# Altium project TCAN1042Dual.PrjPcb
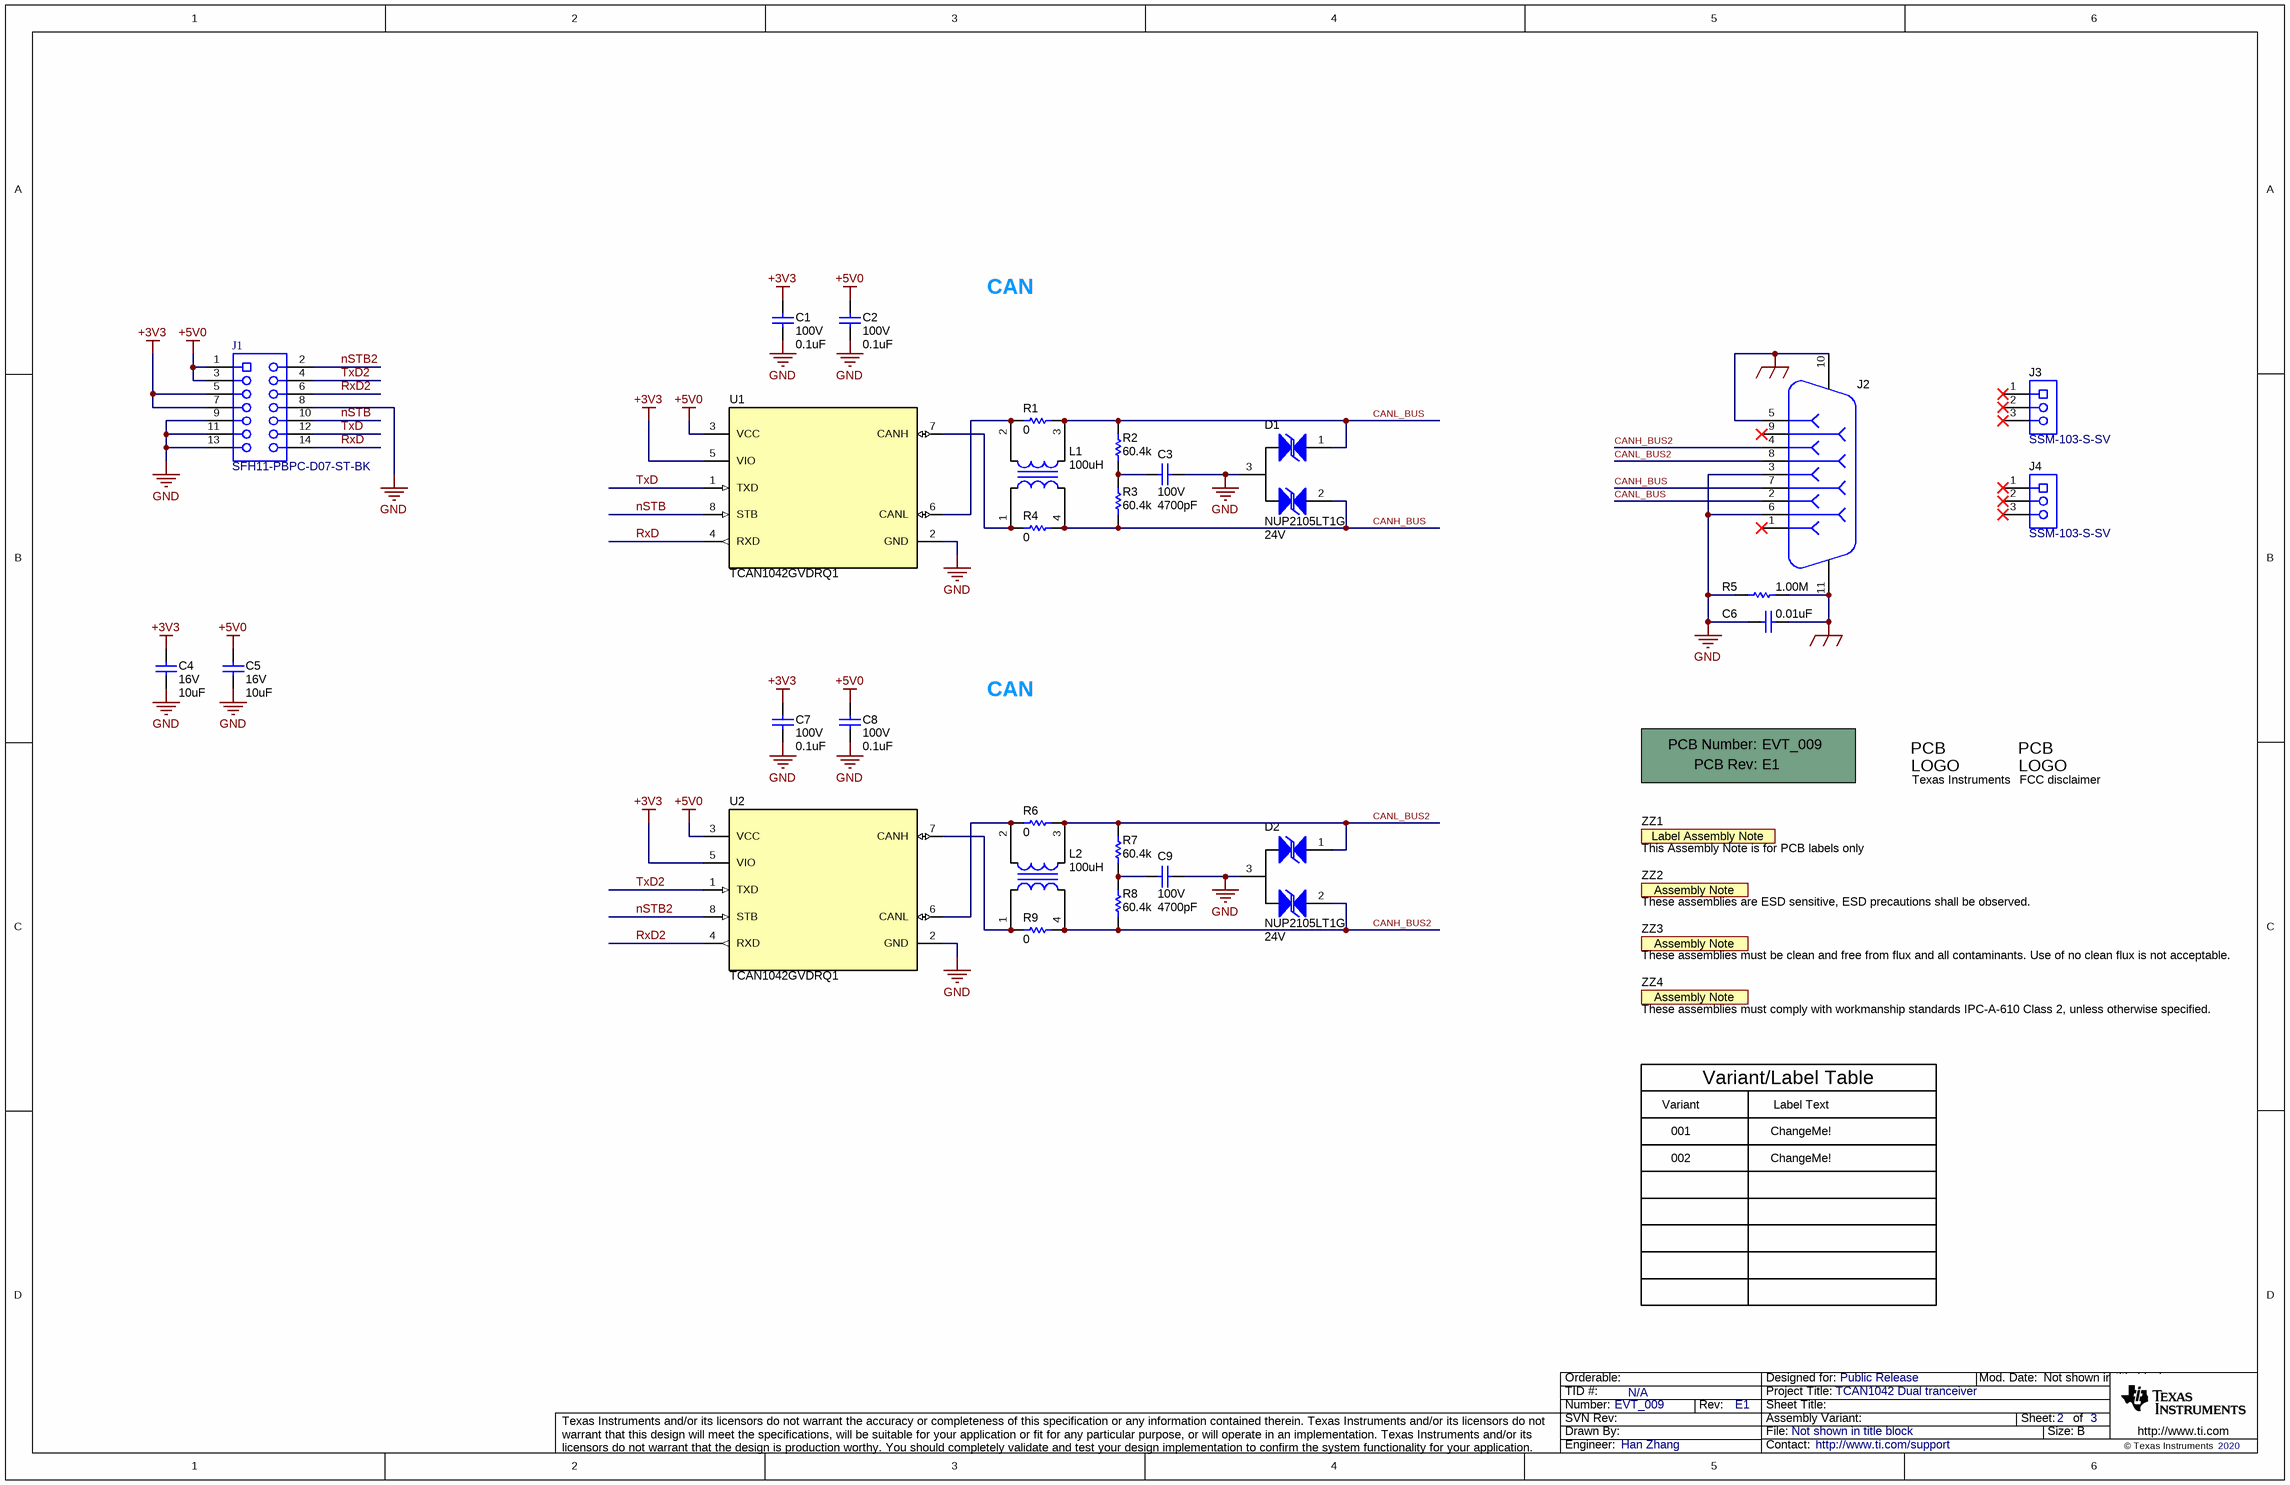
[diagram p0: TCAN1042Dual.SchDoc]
CopyrightYear: 2020; PCB_Layout: Han Zhang; PCB_Rev: E1; PRJ_Customer: Public Release; PRJ_Engineer: Han Zhang; PRJ_Number: EVT_009; PRJ_Title: TCAN1042 Dual tranceiver; SCH_Rev: E1; TechSupport: http://www.ti.com/support; TID: N/A
1 sheet, 35 parts. Net scope: global (net labels, ports and power ports of the same name join across sheets).
Board file: TlCAN1042Dual.PcbDoc

## Sheet TCAN1042Dual.SchDoc
size 431 x 279 mm; Date: Not shown in title block; ApprovedBy: Not shown in title block; CheckedBy: Not shown in title block; Author: Not shown in title block; CompanyName: Not shown in title block; Engineer: Not shown in title block; Organization: Not shown in title block; Address1: Not shown in title block; Address2: Not shown in title block; Address3: Not shown in title block; Address4: Not shown in title block; DocumentNumber: 2; Revision: Use project parameter SCH_Rev; SheetNumber: 2; SheetTotal: 3; PageSetup: Record=PageOptions¦CenterHorizontal=True¦CenterVertical=True¦PrintScale=1.00¦XCorrection=1.00¦YCorrection=1.00¦PrintKind=0¦BorderSize=5000000¦LeftOffset=0¦BottomOffset=0¦Orientation=2¦PaperLength=1000¦PaperWidth=1000¦Scale=100¦PaperSource=15¦PrintQuality=600¦MediaType=1¦DitherType=10¦PaperKind=Letter¦PrintScaleMode=1

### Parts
!PCB1  Printed Circuit Board  (value not drawn)  (mechanical)
C1  VDC_V: 100V  ValueDisplayed: 0.1uF  [0603]  (hidden comment: GRM188R72A104KA35D)
C2  VDC_V: 100V  ValueDisplayed: 0.1uF  [0603]  (hidden comment: GRM188R72A104KA35D)
C3  VDC_V: 100V  ValueDisplayed: 4700pF  [0603]  (hidden comment: CGA3E2X7R2A472K080AA)
C4  VDC_V: 16V  ValueDisplayed: 10uF  [0805_HV]  (hidden comment: CL21B106KOQNNNE)
C5  VDC_V: 16V  ValueDisplayed: 10uF  [0805_HV]  (hidden comment: CL21B106KOQNNNE)
C6  ValueDisplayed: 0.01uF  [1206]  (hidden comment: 12061C103JAT2A)
C7  VDC_V: 100V  ValueDisplayed: 0.1uF  [0603]  (hidden comment: GRM188R72A104KA35D)
C8  VDC_V: 100V  ValueDisplayed: 0.1uF  [0603]  (hidden comment: GRM188R72A104KA35D)
C9  VDC_V: 100V  ValueDisplayed: 4700pF  [0603]  (hidden comment: CGA3E2X7R2A472K080AA)
D1  NUP2105LT1G  value 24V  [SOT-23]
D2  NUP2105LT1G  value 24V  [SOT-23]
J1  SFH11-PBPC-D07-ST-BK  [Sullins_SFH11-xxxC-D07-ST-BK]
J2  5747840-5  [TE_5747840-5]  (value not drawn)
J3  SSM-103-S-SV  [Samtec_SSM-103-x-SV]
J4  SSM-103-S-SV  [Samtec_SSM-103-x-SV]
L1  ValueDisplayed: 100uH  [ACT45B]  (hidden comment: ACT45B-101-2P-TL003)
L2  ValueDisplayed: 100uH  [ACT45B]  (hidden comment: ACT45B-101-2P-TL003)
Logo1  Texas Instruments  [TI_Stacked_Overlay_Small]  (no BOM)
Logo2  FCC disclaimer  [FCC_disclaimer]  (no BOM)
R1  ValueDisplayed: 0  [0603]  (hidden comment: RMCF0603ZT0R00)
R2  ValueDisplayed: 60.4k  [0603]  (hidden comment: CRCW060360K4FKEA)
R3  ValueDisplayed: 60.4k  [0603]  (hidden comment: CRCW060360K4FKEA)
R4  ValueDisplayed: 0  [0603]  (hidden comment: RMCF0603ZT0R00)
R5  ValueDisplayed: 1.00M  [0402S]  (hidden comment: ERJ-2RKF1004X)
R6  ValueDisplayed: 0  [0603]  (hidden comment: RMCF0603ZT0R00)
R7  ValueDisplayed: 60.4k  [0603]  (hidden comment: CRCW060360K4FKEA)
R8  ValueDisplayed: 60.4k  [0603]  (hidden comment: CRCW060360K4FKEA)
R9  ValueDisplayed: 0  [0603]  (hidden comment: RMCF0603ZT0R00)
U1  TCAN1042GVDRQ1  [D0008A_L]
U2  TCAN1042GVDRQ1  [D0008A_L]
ZZ1  This Assembly Note is for PCB labels only  [AssemblyNoteLabel]  (no BOM)
ZZ2  These assemblies are ESD sensitive, ESD precautions shall be observed.  [AssemblyNote]  (no BOM)
ZZ3  These assemblies must be clean and free from flux and all contaminants. Use of no clean flux is not acceptable.  [AssemblyNote]  (no BOM)
ZZ4  These assemblies must comply with workmanship standards IPC-A-610 Class 2, unless otherwise specified.  [AssemblyNote]  (no BOM)

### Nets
+3V3: C1.1 C4.1 C7.1 J1.5 J1.7 U1.5(VIO) U2.5(VIO)
+5V0: C2.1 C5.1 C8.1 J1.1 J1.3 U1.3(VCC) U2.3(VCC)
GND: C1.2 C2.2 C3.1 C4.2 C5.2 C6.2 C7.2 C8.2 C9.1 D1.3 D2.3 J1.8 J1.9 J1.11 J1.13 J2.3 J2.6 R5.1 U1.2(GND) U2.2(GND)
SHIELD_GND: C6.1 J2.5 J2.10 J2.11 R5.2
CANH_BUS: D1.2 J2.7 L1.4 R3.1 R4.2
CANH_BUS2: D2.2 J2.4 L2.4 R8.1 R9.2
CANL_BUS: D1.1 J2.2 L1.3 R1.2 R2.2
CANL_BUS2: D2.1 J2.8 L2.3 R6.2 R7.2
nSTB: J1.10 U1.8(STB)
nSTB2: J1.2 U2.8(STB)
RxD: J1.14 U1.4(RXD)
RxD2: J1.6 U2.4(RXD)
TxD: J1.12 U1.1(TXD)
TxD2: J1.4 U2.1(TXD)
NetC3_2: C3.2 R2.1 R3.2
NetC9_2: C9.2 R7.1 R8.2
NetL1_1: L1.1 R4.1 U1.7(CANH)
NetL1_2: L1.2 R1.1 U1.6(CANL)
NetL2_1: L2.1 R9.1 U2.7(CANH)
NetL2_2: L2.2 R6.1 U2.6(CANL)

Not connected (* = marked no-connect by the designer): J2 1* 9*; J3 1* 2* 3*; J4 1* 2* 3*

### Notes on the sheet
- CAN
- Variant
- Variant/Label Table
- Label Text
- 001
- 002
- ChangeMe!

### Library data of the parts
!PCB1 = CMP-0003618-2: Manufacturer: Any; PartNumber: EVT_009
C1 C2 C7 C8 = CMP-0007469-4: CAP, CERM, 0.1 uF, 100 V, +/- 10%, X7R, 0603; Manufacturer: MuRata; TaMin_C: -55°C; Polarized: N; SizeAreaWB_mm2: 4.68; Value1: Unknown; U/M: EA; Value: 0.1uF; TaMax_C: 125°C; SizeZ_mm: 1; SizeX_mm: 1.6; SizeY_mm: 0.8; SizeArea_mm2: 1.28; Cap_F: 100nF; AEC Category: Q200
C3 C9 = CMP-0007088-4: CAP, CERM, 4700 pF, 100 V, +/- 10%, X7R, AEC-Q200 Grade 1, 0603; Manufacturer: TDK; TaMin_C: -55°C; ESR_ohm: 4.69862d; Polarized: N; SizeAreaWB_mm2: 4.68; Value1: 0.469862 ohm; U/M: EA; Value: 4700pF; TaMax_C: 125°C; SizeZ_mm: 1; SizeX_mm: 1.6; SizeY_mm: 0.8; SizeArea_mm2: 1.28; AEC Qualified: Y; Cap_F: 4.7nF; IRMS_A: 3.2335dA; AEC Category: Q200
C4 C5 = CMP-0007995-2: CAP, CERM, 10 uF, 16 V, +/- 10%, X7R, 0805; Manufacturer: Samsung Electro-Mechanics; TaMin_C: -55°C; Polarized: N; SizeAreaWB_mm2: 6.75; Value1: Unknown; U/M: EA; Value: 10uF; TaMax_C: 125°C; SizeZ_mm: 1.45; SizeX_mm: 2; SizeY_mm: 1.25; Cap_Case: 0805; SizeArea_mm2: 2.5; CompType: Capacitor; Cap_F: 10µF; AEC Category: Q200
C6 = CMP-0008484-2: CAP, CERM, 0.01 uF, 100 V, +/- 5%, X7R, 1206; Manufacturer: AVX; TaMin_C: -55°C; ESR_ohm: 1.19d; Polarized: N; SizeAreaWB_mm2: 10.92; Value1: 0.119 ohm; U/M: EA; Value: 0.01uF; TaMax_C: 125°C; SizeZ_mm: 1.35; SizeX_mm: 3.2; SizeY_mm: 1.6; Value2: 100V; SizeArea_mm2: 5.12; Cap_F: 10nF; AEC Category: Q200
D1 D2 = CMP-0005919-2: Diode, TVS, Bi, 24 V, SOT-23; Manufacturer: ON Semiconductor; Power_W: 350mW; SizeAreaWB_mm2: 14; Value1: 0.35W; U/M: EA; SizeZ_mm: 1.1; SizeX_mm: 2.5; SizeY_mm: 3; SizeArea_mm2: 7.5; AEC Category: Q101
J1 = CMP-0054668-1: Receptacle, 2.54mm, 7x2, Gold, Black, TH; Manufacturer: Sullins Connector Solutions; CNHeader: FALSE; Current_A: 3A; Gender: Female; Voltage_V: 1kV; CompType: Socket Strip; Row_Count: 2; RowSpacing_mm: 2.54; CT: TRUE; Cert_UL: Y
J2 = CMP-0054938-4: D-Sub, 2.74mm, 9 Position, R/A, TH; Manufacturer: TE Connectivity; CNHeader: FALSE; Gender: Male; Row_Count: 2; Pitch_mm: 2.74; ContactFinish: Gold; CT: TRUE; Cert_UL: Y
J3 J4 = CMP-0078183-1: Receptacle, 2.54mm, 3x1, Gold with Tin tail, SMT; Manufacturer: Samtec; Pitch_mm: 2.54; Gender: Female; Cert_CSA: Y; Voltage_V: 405V; Current_A: 5.2A; Row_Count: 1; CompType: Socket Strip
L1 L2 = CMP-0062430-2: Inductor, Ferrite, 100 uH, 0.15 A, 2 ohm, SMD; Manufacturer: TDK; Isat: 0.15A @ % inductance drop; Green_Lifecycle: Active; SizeAreaWB_mm2: 23.1; DCR_ohm: 2; Green_REACh: Passed; Value1: 2 ohm; Value: 100uH; Imax_A: 1.5dA; SizeZ_mm: 3; SizeX_mm: 4.5; SizeY_mm: 3.2; Value2: 0.15A; SizeArea_mm2: 14.4; Ind_H: 100µH; AEC Category: Q200
Logo1 = CMP-0074838-1: Texas Instrument Corporate Signature; SymbolCreator: a0412235; Lib Reference: TI_Logo; Library Reference: Logo
Logo2 = CMP-0074847-1: FCC_disclaimer; Library Reference: Logo
R1 R4 R6 R9 = CMP-0023343-3: RES, 0, 1%, 0.1 W, AEC-Q200 Grade 0, 0603; Manufacturer: Stackpole Electronics Inc; Power_W: 100mW; TempCo: ppm/C; U/M: EA; Value: 0; SizeX_mm: 1.6; SizeY_mm: 0.8; SizeZ_mm: 1; Value2: 0.1W; SizeArea_mm2: 1.28; AEC Qualified: Y; AEC Category: Q200
R2 R3 R7 R8 = CMP-0022532-4: RES, 60.4 k, 1%, 0.1 W, AEC-Q200 Grade 0, 0603; Manufacturer: Vishay-Dale; Power_W: 100mW; TempCo: 100 ppm/C; Value_Code: 60k4; Value: 60.4k; EIA_Code: E96; SizeX_mm: 1.6; SizeY_mm: 0.8; SizeZ_mm: 1; Value2: 0.1W; SizeArea_mm2: 1.28; AEC Qualified: Y; VDC_V: 75V; AEC Category: Q200; AEC Grade: 0
R5 = CMP-0026660-1: RES, 1.00 M, 1%, 0.1 W, 0402; Manufacturer: Panasonic; Power_W: 100mW; TempCo: 100 ppm/C; Value_Code: 1M00; U/M: EA; Value: 1.00Meg; EIA_Code: E96; Res_ohm: 1M; SizeX_mm: 1; SizeY_mm: 0.5; SizeZ_mm: 0.6; Value2: 0.1W; VDC_V: 50V; AEC Category: Q200
U1 U2 = CMP-0075989-1: Automotive Fault Protected CAN Transceiver With Flexible Data-Rate, D0008A (SOIC-8); Manufacturer: Texas Instruments; Alternate PartNumber: TCAN1042GVDQ1; SizeAreaWB_mm2: 56.58; SizeArea_mm2: 30.38; SizeZ_mm: 1.75; SizeY_mm: 6.2; U/M: EA; CompType: IC; SizeX_mm: 4.9
ZZ1 = CMP-0003616-3
ZZ2 = CMP-0077236-1
ZZ3 = CMP-0077237-1
ZZ4 = CMP-0077238-1

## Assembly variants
001: not fitted R1 R5 R6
